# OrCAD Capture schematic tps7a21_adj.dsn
size A
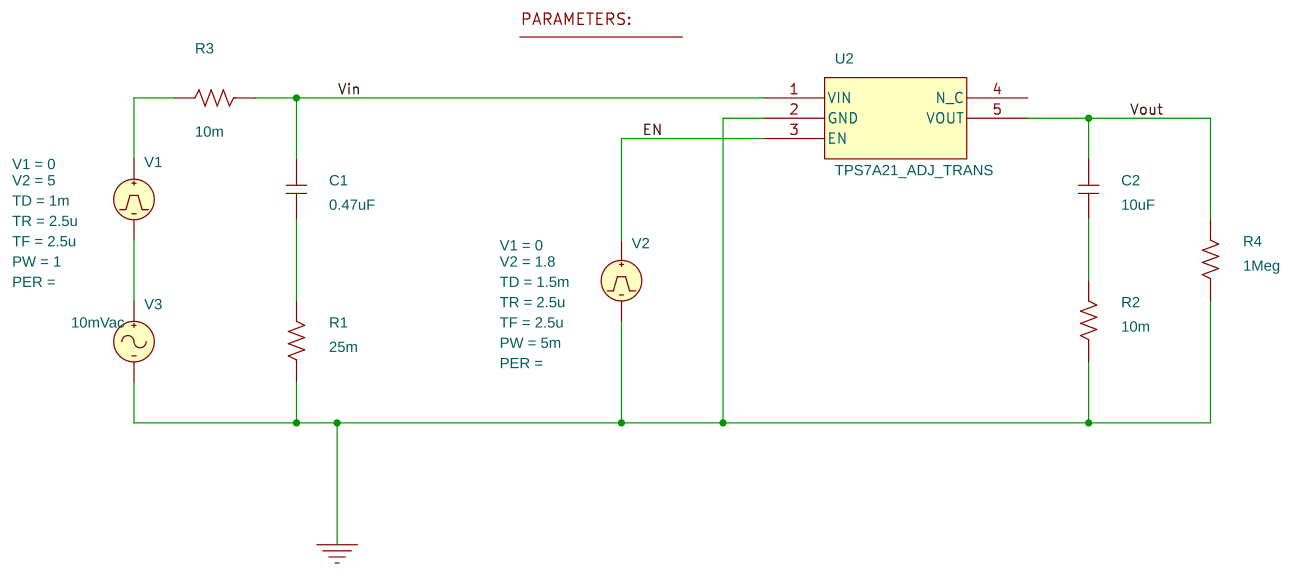
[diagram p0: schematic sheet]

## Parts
1  PARAM
C1  0.47uF  [cap196]
C2  10uF  [cap196]
R1  25m  [AXRC05]
R2  10m  [AXRC05]
R3  10m  [AXRC05]
R4  1Meg  [AXRC05]
U2  TPS7A21_ADJ_TRANS
V1  VPULSE
V2  VPULSE
V3  VAC

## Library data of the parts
1 = PARAM: V_out: 0.8
C1 C2 = C
R1-R4 = R
U2 = TPS7A21_ADJ_TRANS
V1 = VPULSE: PW: 1; TD: 1m; TF: 2.5u; TR: 2.5u; V1: 0; V2: 5
V2 = VPULSE: PW: 5m; TD: 1.5m; TF: 2.5u; TR: 2.5u; V1: 0; V2: 1.8
V3 = VAC: ACMAG: 10mVac

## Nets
Vin: C1.2 R3.1 U2.1(VIN)
0: R1.1 R2.1 R4.1 U2.2(GND) V2.2(-) V3.2(-)
EN: U2.3(EN) V2.1(+)
Vout: C2.2 R4.2 U2.5(VOUT)
N01455: C2.1 R2.2
N01459: C1.1 R1.2
N01961: R3.2 V1.1(+)
N07291: V1.2(-) V3.1(+)

Not connected (* = marked no-connect by the designer): U2 4(N_C)
